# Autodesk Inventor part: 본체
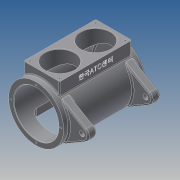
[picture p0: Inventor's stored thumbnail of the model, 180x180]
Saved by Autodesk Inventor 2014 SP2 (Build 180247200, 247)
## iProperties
Created: 2016-11
Part Number: 본체
Material: 알루미늄 6061
Document SubType Name: Modeling
Designer: mduedu
Density: 2.71 g/cm^3
Appearance: 기본값
Mass: 2578.28 g
Surface Area: 1746.6 cm^2
Volume: 951.394 cm^3
Author: mduedu
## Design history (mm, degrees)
sketch "스케치1"
  geometry: C1 r 65 at (0, 0); 1 further point
  constraints: 1 centre point, 1 coincident
  dimensions: "d119" = 130 diameter of C1
extrude "돌출1" new body sketch "스케치1" distance "d3" = 98; taper "d4" = 0 deg; dims "d132" = 97, "d133" = 0
feature "쉘1" dims "d120" = 12, "d134" = 8
node "작업 평면2"
sketch "스케치13"
  geometry: L1 (42.5, 85)-(-42.5, 85); L2 (-42.5, 85)-(-42.5, -85); L3 (-42.5, -85)-(42.5, -85); L4 (42.5, -85)-(42.5, 85); 2 further points
  constraints: 8 end point, 2 parallel, 1 horizontal, 1 midpoint, 1 perpendicular, 1 vertical alignment
  dimensions: "d122" = 170 distance of L1.end L2.end; "d124" = 85 distance of L2.end L3.end; "d125" = 85 distance from line of point (0, 0) L1 (= 0.5 x d122)
extrude "돌출11" join sketch "스케치13" stored distance "d126" = 10; taper "d127" = 0 deg
sketch "스케치14"
  geometry: L1 (65, 97)-(-65, 97) reference; C1 r 35 at (0, 42.5); 1 further point
  constraints: 1 centre point, 1 vertical alignment
  dimensions: "d128" = 70 diameter of C1; "d129" = 54.5 distance from line of C1.centre L1
extrude "돌출12" cut sketch "스케치14" stored distance "d130" = 10; taper "d131" = 0 deg
sketch "스케치15"
  geometry: C1 r 53 at (0, 0) reference; 1 further point
extrude "돌출13" cut sketch "스케치15" stored distance "d135" = 10; taper "d136" = 0 deg
chamfer "모따기1" distance "d54" = 1; stored, may be unused: second distance "d55" = 2, angle "d56" = 45 deg
sketch "스케치8"
  geometry: C1 r 23 at (0, 0); C2 r 65 at (0, 0) reference; 1 further point
  constraints: 1 centre point, 1 concentric
  dimensions: "d57" = 46 diameter of C1
extrude "돌출8" join sketch "스케치8" distance "d58" = 14; taper "d59" = 0 deg
feature "면 기울기1" dims angle "d202" = 10 deg
hole "구멍3" diameter "d62" = 24; stored, may be unused: countersink angle "d66" = 90 deg, drill point angle "d68" = 0 deg; dims "d63" = 6, "d64" = 28, "d65" = 8, "d67" = 14, "d169" = 10, "d170" = 10
fillet "모깎기11" dims "d69" = 3
fillet "모깎기12" dims "d70" = 3
fillet "모깎기13" dims "d71" = 0.3
chamfer "모따기2" distance "d72" = 1; stored, may be unused: second distance "d73" = 2, angle "d74" = 45 deg
node "작업 평면3"
sketch "스케치16"
  geometry: L1 (-42.5, -80)-(52.5, -80); L2 (-42.5, -80)-(24.675, -12.825); L3 (-42.5, -80)-(24.675, -147.175); L4 (3.462, -34.038)-(60.057, -67.042); L5 (3.462, -125.962)-(60.057, -92.958); A1 r 65 centre (-42.5, -80) between (3.462, -34.038) and (3.462, -125.962) reference; A2 r 65 centre (-42.5, -80) between (3.462, -125.962) and (3.462, -34.038); A3 r 95 centre (-42.5, -80) between (52.5, -80) and (24.675, -147.175); A4 r 15 centre (52.5, -80) between (60.057, -67.042) and (60.057, -92.958); 1 further point
  constraints: 10 end point, 9 point on circle, 3 centre point, 3 coincident, 2 point on line, 2 tangent, 1 horizontal
  dimensions: "d140" = 45 deg angle of L3 L1; "d141" = 45 deg angle of L2 L1; "d194" = 30 radial gap between concentric circles of A3 A1; "d195" = 30 diameter of A4
extrude "돌출14" join sketch "스케치16" distance "d143" = 20; taper "d144" = 0 deg
fillet "모깎기25" dims "d196" = 3
fillet "모깎기26" dims "d197" = 3
sketch "스케치22"
  geometry: C1 r 6 at (52.5, -80); A1 r 15 centre (52.5, -80) between (60.057, -92.958) and (60.057, -67.042) reference; 1 further point
  constraints: 1 centre point, 1 coincident
  dimensions: "d198" = 12 diameter of C1
extrude "돌출17" cut sketch "스케치22" stored distance "d200" = 10; taper "d201" = 0 deg
fillet "모깎기20" dims "d159" = 3
fillet "모깎기21" dims "d160" = 3
fillet "모깎기22" dims "d161" = 3
node "작업 평면4"
sketch "스케치18"
  geometry: L1 (-42.5, 65)-(42.5, 65); L2 (42.5, 65)-(42.5, -65); L3 (42.5, -65)-(-42.5, -65); L4 (-42.5, -65)-(-42.5, 65); 2 further points
  constraints: 8 end point, 2 parallel, 1 horizontal, 1 midpoint, 1 perpendicular, 1 vertical alignment
  dimensions: "d162" = 130 distance of L1.end L2.end; "d164" = 85 distance of L2.end L3.end; "d165" = 65 distance from line of point (0, 0) L1 (= 0.5 x d162)
extrude "돌출16" cut sketch "스케치18" stored distance "d166" = 15; taper "d167" = 0 deg
fillet "모깎기23" dims "d168" = 10
fillet "모깎기24" dims "d173" = 3
sketch "스케치19"
  geometry: 4 further points
  constraints: 4 other
hole "구멍6" sketch "스케치19" at (0, -59), (59, 0), (-59, 0), (0, 59) diameter "d174" = 3.242; stored, may be unused: countersink angle "d178" = 90 deg, drill point angle "d180" = 120 deg; dims "d175" = 7, "d176" = 4, "d177" = 2, "d179" = 9
sketch "스케치20"
  geometry: L1 (35, -77.5)-(-35, -77.5); L2 (-35, -77.5)-(-35, -7.5); L3 (-35, -7.5)-(35, -7.5); L4 (35, -7.5)-(35, -77.5); L5 (35, -77.5)-(-35, -7.5); L6 (-35, -77.5)-(35, -7.5); C1 r 36 at (0, -42.5) reference; 3 further points
  constraints: 12 end point, 2 coincident, 2 midpoint, 2 parallel, 1 horizontal, 1 perpendicular
  dimensions: "d181" = 70 distance of L2.end L3.end; "d182" = 70 distance of L1.end L2.end
hole "구멍7" sketch "스케치20" at (-35, -77.5), (35, -77.5) diameter "d183" = 3.242; stored, may be unused: countersink angle "d187" = 90 deg, drill point angle "d189" = 118 deg; dims "d184" = 7, "d185" = 4, "d186" = 2, "d188" = 9
sketch "스케치21"
  geometry: L1 (164, 0)-(0, 0) reference; L2 (-3, 0)-(-3, -24.649) reference; 3 further points
  constraints: 1 midpoint, 1 vertical alignment, 1 other
  dimensions: "d190" = 15 distance from line of point (82, -15) L1; "d191" = 85 distance from line of point (82, 0) L2 (derived)
feature "엠보싱2" sketch "스케치21" dims "d119" = 130, "d192" = 0.5, "d193" = 0
node "솔리드1"
mirror "대칭5"
mirror "대칭6"
mirror "대칭7"
